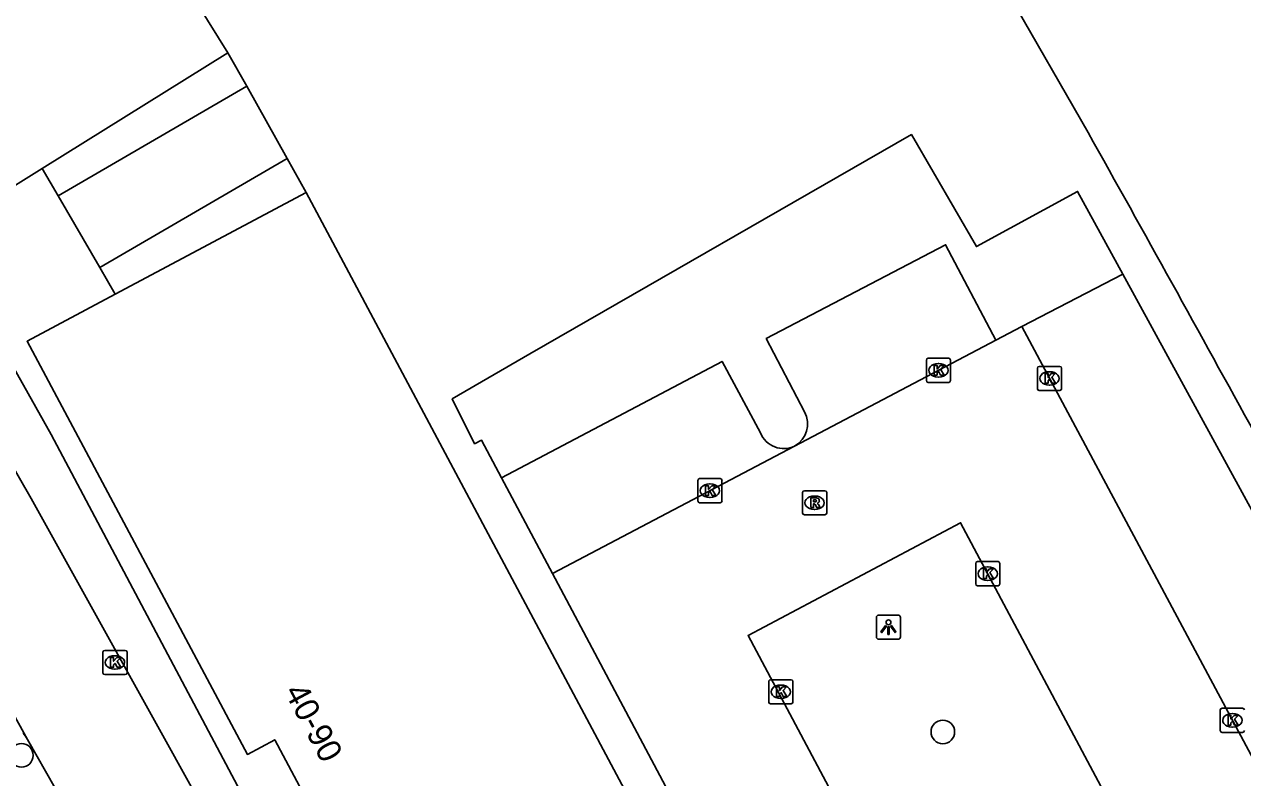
# Model space of a CAD drawing. Extents: x 160304 to 160954, y 383686 to 384161.
# Drawn here: x 160761.5 to 160812, y 383967.6 to 383998.8 of the extents above; entities that cross this region are included whole.
import ezdxf

# ---------------------------------------------------------------- set-up
doc = ezdxf.new("R2010")
doc.units = 0
for name, color, linetype in [('IMGEO_Boom', 7, 'Continuous'), ('IMGEO_Kolk', 7, 'Continuous'), ('IMGEO_Lichtpunt', 7, 'Continuous'), ('IMGEO_Pand', 7, 'Continuous'), ('IMGEO_Pand_nummerreeks', 7, 'Continuous'), ('IMGEO_Pand_overbouw', 7, 'Continuous'), ('IMGEO_Parkeervlak_open', 7, 'Continuous'), ('IMGEO_Rijbaan_lokaal_open', 7, 'Continuous'), ('IMGEO_Rioolput', 7, 'Continuous'), ('IMGEO_Voetpad_open', 7, 'Continuous')]:
    doc.layers.add(name, color=color, linetype=linetype)

msp = doc.modelspace()

# ---------------------------------------------------------------- linework, layer by layer
at = {"layer": 'IMGEO_Boom'}
for centre in [(160799.535, 383969.454), (160761.339, 383968.483)]:
    msp.add_circle(centre, 0.489, dxfattribs=at)
at = {"layer": 'IMGEO_Kolk'}
for p, q in [((160798.927, 383984.937), (160799.779, 383984.937)), ((160798.852, 383984.011), (160798.852, 383984.863)), ((160799.34, 383984.717), (160799.365, 383984.717)), ((160799.853, 383984.863), (160799.853, 383984.011)), ((160803.456, 383983.674), (160803.456, 383984.526)), ((160803.531, 383984.6), (160804.383, 383984.6)), ((160804.457, 383984.526), (160804.457, 383983.674)), ((160799.779, 383983.937), (160798.927, 383983.937)), ((160799.363, 383984.157), (160799.338, 383984.157)), ((160803.944, 383984.38), (160803.969, 383984.38)), ((160804.383, 383983.6), (160803.531, 383983.6)), ((160803.967, 383983.82), (160803.942, 383983.82)), ((160789.38, 383979.024), (160789.38, 383979.876)), ((160789.455, 383979.95), (160790.307, 383979.95)), ((160790.381, 383979.876), (160790.381, 383979.024)), ((160789.868, 383979.73), (160789.893, 383979.73)), ((160790.307, 383978.95), (160789.455, 383978.95)), ((160789.891, 383979.17), (160789.866, 383979.17)), ((160800.897, 383975.584), (160800.897, 383976.436)), ((160800.972, 383976.51), (160801.824, 383976.51)), ((160801.898, 383976.436), (160801.898, 383975.584)), ((160801.385, 383976.29), (160801.41, 383976.29)), ((160801.824, 383975.51), (160800.972, 383975.51)), ((160801.408, 383975.73), (160801.383, 383975.73)), ((160764.791, 383972.831), (160765.643, 383972.831)), ((160764.716, 383971.905), (160764.716, 383972.757)), ((160765.204, 383972.611), (160765.229, 383972.611)), ((160765.717, 383972.757), (160765.717, 383971.905)), ((160765.643, 383971.831), (160764.791, 383971.831)), ((160765.227, 383972.051), (160765.202, 383972.051)), ((160792.32, 383970.69), (160792.32, 383971.542)), ((160792.395, 383971.616), (160793.247, 383971.616)), ((160792.808, 383971.396), (160792.833, 383971.396)), ((160793.321, 383971.542), (160793.321, 383970.69)), ((160792.831, 383970.836), (160792.806, 383970.836)), ((160793.247, 383970.616), (160792.395, 383970.616)), ((160811.037, 383969.51), (160811.037, 383970.362)), ((160811.112, 383970.436), (160811.964, 383970.436)), ((160811.525, 383970.216), (160811.55, 383970.216)), ((160811.964, 383969.436), (160811.112, 383969.436)), ((160811.548, 383969.656), (160811.523, 383969.656))]:
    msp.add_line(p, q, dxfattribs=at)
for points in [[(160798.927, 383984.937), (160799.779, 383984.937)], [(160798.852, 383984.011), (160798.852, 383984.863)], [(160799.173, 383984.637), (160799.296, 383984.637), (160799.296, 383984.486), (160799.426, 383984.637), (160799.59, 383984.637), (160799.444, 383984.486), (160799.597, 383984.237), (160799.445, 383984.237), (160799.36, 383984.401), (160799.296, 383984.334), (160799.296, 383984.237), (160799.173, 383984.237), (160799.173, 383984.637)], [(160799.853, 383984.863), (160799.853, 383984.011)], [(160803.456, 383983.674), (160803.456, 383984.526)], [(160803.531, 383984.6), (160804.383, 383984.6)], [(160804.457, 383984.526), (160804.457, 383983.674)], [(160799.779, 383983.937), (160798.927, 383983.937)], [(160803.777, 383984.3), (160803.9, 383984.3), (160803.9, 383984.149), (160804.03, 383984.3), (160804.194, 383984.3), (160804.048, 383984.149), (160804.201, 383983.9), (160804.049, 383983.9), (160803.964, 383984.064), (160803.9, 383983.997), (160803.9, 383983.9), (160803.777, 383983.9), (160803.777, 383984.3)], [(160804.383, 383983.6), (160803.531, 383983.6)], [(160789.38, 383979.024), (160789.38, 383979.876)], [(160789.455, 383979.95), (160790.307, 383979.95)], [(160790.381, 383979.876), (160790.381, 383979.024)], [(160789.701, 383979.65), (160789.824, 383979.65), (160789.824, 383979.499), (160789.954, 383979.65), (160790.118, 383979.65), (160789.972, 383979.499), (160790.125, 383979.25), (160789.973, 383979.25), (160789.888, 383979.414), (160789.824, 383979.347), (160789.824, 383979.25), (160789.701, 383979.25), (160789.701, 383979.65)], [(160790.307, 383978.95), (160789.455, 383978.95)], [(160800.897, 383975.584), (160800.897, 383976.436)], [(160800.972, 383976.51), (160801.824, 383976.51)], [(160801.898, 383976.436), (160801.898, 383975.584)], [(160801.218, 383976.21), (160801.341, 383976.21), (160801.341, 383976.059), (160801.471, 383976.21), (160801.635, 383976.21), (160801.489, 383976.059), (160801.642, 383975.81), (160801.49, 383975.81), (160801.405, 383975.974), (160801.341, 383975.907), (160801.341, 383975.81), (160801.218, 383975.81), (160801.218, 383976.21)], [(160801.824, 383975.51), (160800.972, 383975.51)], [(160764.791, 383972.831), (160765.643, 383972.831)], [(160764.716, 383971.905), (160764.716, 383972.757)], [(160765.037, 383972.531), (160765.16, 383972.531), (160765.16, 383972.38), (160765.29, 383972.531), (160765.454, 383972.531), (160765.308, 383972.38), (160765.461, 383972.131), (160765.309, 383972.131), (160765.224, 383972.295), (160765.16, 383972.228), (160765.16, 383972.131), (160765.037, 383972.131), (160765.037, 383972.531)], [(160765.717, 383972.757), (160765.717, 383971.905)], [(160765.643, 383971.831), (160764.791, 383971.831)], [(160792.32, 383970.69), (160792.32, 383971.542)], [(160792.395, 383971.616), (160793.247, 383971.616)], [(160792.641, 383971.316), (160792.764, 383971.316), (160792.764, 383971.165), (160792.894, 383971.316), (160793.058, 383971.316), (160792.912, 383971.165), (160793.065, 383970.916), (160792.913, 383970.916), (160792.828, 383971.08), (160792.764, 383971.013), (160792.764, 383970.916), (160792.641, 383970.916), (160792.641, 383971.316)], [(160793.321, 383971.542), (160793.321, 383970.69)], [(160793.247, 383970.616), (160792.395, 383970.616)], [(160811.037, 383969.51), (160811.037, 383970.362)], [(160811.112, 383970.436), (160811.964, 383970.436)], [(160811.358, 383970.136), (160811.481, 383970.136), (160811.481, 383969.985), (160811.611, 383970.136), (160811.775, 383970.136), (160811.629, 383969.985), (160811.782, 383969.736), (160811.63, 383969.736), (160811.545, 383969.9), (160811.481, 383969.833), (160811.481, 383969.736), (160811.358, 383969.736), (160811.358, 383970.136)], [(160811.964, 383969.436), (160811.112, 383969.436)]]:
    msp.add_lwpolyline(points, dxfattribs=at)
for centre, start, end in [((160798.929, 383984.861), 91.552, 178.448), ((160798.929, 383984.861), 91.552, 178.448), ((160799.777, 383984.861), 1.552, 88.448), ((160799.777, 383984.861), 1.552, 88.448), ((160803.533, 383984.524), 91.552, 178.448), ((160803.533, 383984.524), 91.552, 178.448), ((160804.381, 383984.524), 1.552, 88.448), ((160804.381, 383984.524), 1.552, 88.448), ((160798.929, 383984.013), 181.552, 268.448), ((160798.929, 383984.013), 181.552, 268.448), ((160799.777, 383984.013), 271.552, 358.448), ((160799.777, 383984.013), 271.552, 358.448), ((160803.533, 383983.676), 181.552, 268.448), ((160803.533, 383983.676), 181.552, 268.448), ((160804.381, 383983.676), 271.552, 358.448), ((160804.381, 383983.676), 271.552, 358.448), ((160789.457, 383979.874), 91.552, 178.448), ((160789.457, 383979.874), 91.552, 178.448), ((160790.305, 383979.874), 1.552, 88.448), ((160790.305, 383979.874), 1.552, 88.448), ((160789.457, 383979.026), 181.552, 268.448), ((160789.457, 383979.026), 181.552, 268.448), ((160790.305, 383979.026), 271.552, 358.448), ((160790.305, 383979.026), 271.552, 358.448), ((160800.974, 383976.434), 91.552, 178.448), ((160800.974, 383976.434), 91.552, 178.448), ((160801.822, 383976.434), 1.552, 88.448), ((160801.822, 383976.434), 1.552, 88.448), ((160800.974, 383975.586), 181.552, 268.448), ((160800.974, 383975.586), 181.552, 268.448), ((160801.822, 383975.586), 271.552, 358.448), ((160801.822, 383975.586), 271.552, 358.448), ((160764.793, 383972.755), 91.552, 178.448), ((160764.793, 383972.755), 91.552, 178.448), ((160765.641, 383972.755), 1.552, 88.448), ((160765.641, 383972.755), 1.552, 88.448), ((160764.793, 383971.907), 181.552, 268.448), ((160764.793, 383971.907), 181.552, 268.448), ((160765.641, 383971.907), 271.552, 358.448), ((160765.641, 383971.907), 271.552, 358.448), ((160792.397, 383971.54), 91.552, 178.448), ((160792.397, 383971.54), 91.552, 178.448), ((160793.245, 383971.54), 1.552, 88.448), ((160793.245, 383971.54), 1.552, 88.448), ((160792.397, 383970.692), 181.552, 268.448), ((160792.397, 383970.692), 181.552, 268.448), ((160793.245, 383970.692), 271.552, 358.448), ((160793.245, 383970.692), 271.552, 358.448), ((160811.114, 383970.36), 91.552, 178.448), ((160811.114, 383970.36), 91.552, 178.448), ((160811.962, 383970.36), 1.552, 88.448), ((160811.962, 383970.36), 1.552, 88.448), ((160811.114, 383969.512), 181.552, 268.448), ((160811.114, 383969.512), 181.552, 268.448), ((160811.962, 383969.512), 271.552, 358.448), ((160811.962, 383969.512), 271.552, 358.448)]:
    msp.add_arc(centre, 0.0765, start, end, dxfattribs=at)
for centre, major_axis, ratio, start_param, end_param in [((160799.339, 383984.437), (-0.387, 0.002), 0.722429, 4.712389, 7.853982), ((160799.364, 383984.437), (-0.39, 0.002), 0.717154, 1.570796, 4.712389), ((160803.943, 383984.1), (-0.387, 0.002), 0.722429, 4.712389, 7.853982), ((160803.968, 383984.1), (-0.39, 0.002), 0.717154, 1.570796, 4.712389), ((160789.867, 383979.45), (-0.387, 0.002), 0.722429, 4.712389, 7.853982), ((160789.892, 383979.45), (-0.39, 0.002), 0.717154, 1.570796, 4.712389), ((160801.384, 383976.01), (-0.387, 0.002), 0.722429, 4.712389, 7.853982), ((160801.409, 383976.01), (-0.39, 0.002), 0.717154, 1.570796, 4.712389), ((160765.203, 383972.331), (-0.387, 0.002), 0.722429, 4.712389, 7.853982), ((160765.228, 383972.331), (-0.39, 0.002), 0.717154, 1.570796, 4.712389), ((160792.807, 383971.116), (-0.387, 0.002), 0.722429, 4.712389, 7.853982), ((160792.832, 383971.116), (-0.39, 0.002), 0.717154, 1.570796, 4.712389), ((160811.524, 383969.936), (-0.387, 0.002), 0.722429, 4.712389, 7.853982), ((160811.549, 383969.936), (-0.39, 0.002), 0.717154, 1.570796, 4.712389)]:
    msp.add_ellipse(centre, major_axis=major_axis, ratio=ratio, start_param=start_param, end_param=end_param, dxfattribs=at)
at = {"layer": 'IMGEO_Lichtpunt'}
for p, q in [((160796.783, 383974.197), (160796.783, 383973.39)), ((160796.783, 383974.197), (160796.783, 383973.39)), ((160797.685, 383974.292), (160796.877, 383974.292)), ((160797.685, 383974.292), (160796.877, 383974.292)), ((160797.779, 383973.39), (160797.779, 383974.197)), ((160797.779, 383973.39), (160797.779, 383974.197)), ((160796.877, 383973.296), (160797.685, 383973.296)), ((160796.877, 383973.296), (160797.685, 383973.296))]:
    msp.add_line(p, q, dxfattribs=at)
for points in [[(160797.157, 383973.861), (160797.196, 383973.833), (160797.008, 383973.571), (160796.97, 383973.598), (160797.157, 383973.861)], [(160797.259, 383973.813), (160797.306, 383973.813), (160797.306, 383973.491), (160797.259, 383973.491), (160797.259, 383973.813)], [(160797.369, 383973.833), (160797.407, 383973.86), (160797.594, 383973.598), (160797.555, 383973.57), (160797.369, 383973.833)]]:
    msp.add_lwpolyline(points, dxfattribs=at)
msp.add_circle((160797.282, 383973.995), 0.0994, dxfattribs=at)
for centre, start, end in [((160796.877, 383974.197), 90, 180), ((160796.877, 383974.197), 90, 180), ((160797.685, 383974.197), 0, 90), ((160797.685, 383974.197), 0, 90), ((160796.877, 383973.39), 180, 270), ((160796.877, 383973.39), 180, 270), ((160797.685, 383973.39), 270, 0), ((160797.685, 383973.39), 270, 360)]:
    msp.add_arc(centre, 0.0946, start, end, dxfattribs=at)
at = {"layer": 'IMGEO_Pand'}
for points in [[(160744.525, 384030.508), (160747.806, 384032.552), (160748.032, 384032.693), (160769.901, 383997.598), (160762.198, 383992.799), (160758.718, 383990.63), (160748.428, 384007.142), (160749.512, 384007.817), (160744.868, 384015.27), (160743.822, 384014.618), (160737.034, 384025.51)], [(160797.022, 384009.201), (160802.29, 384000), (160805.557, 383994.294)], [(160772.358, 383993.214), (160764.587, 383988.694), (160762.857, 383991.667), (160770.681, 383996.207), (160772.358, 383993.214)], [(160780.961, 383949.257), (160774.814, 383960.781), (160775.968, 383961.397), (160771.843, 383969.13), (160770.706, 383968.524), (160761.577, 383985.638), (160765.23, 383987.587), (160773.144, 383991.809), (160792.547, 383955.437), (160789.439, 383953.779)]]:
    msp.add_lwpolyline(points, dxfattribs=at)
msp.add_arc((159123.204, 383053.921), 1927.333, 28.779303, 29.203562, dxfattribs=at)
at = {"layer": 'IMGEO_Pand_overbouw'}
for points in [[(160770.681, 383996.207), (160769.901, 383997.598), (160762.198, 383992.799), (160762.857, 383991.667)], [(160764.587, 383988.694), (160765.23, 383987.587), (160773.144, 383991.809), (160772.358, 383993.214)]]:
    msp.add_lwpolyline(points, close=True, dxfattribs=at)
at = {"layer": 'IMGEO_Parkeervlak_open'}
for points in [[(160806.997, 383988.421), (160817.543, 383969.142), (160814.927, 383967.761), (160817.081, 383963.773), (160819.647, 383965.18), (160824.324, 383956.417), (160820.023, 383954.079)], [(160783.352, 383976.011), (160781.236, 383979.986)]]:
    msp.add_lwpolyline(points, dxfattribs=at)
at = {"layer": 'IMGEO_Rijbaan_lokaal_open'}
for points in [[(160750.394, 383998.089), (160755.01, 383990.819), (160761.742, 383979.128), (160773.706, 383957.589), (160774.263, 383956.197)], [(160747.642, 383992.973), (160752.22, 383985.59), (160753.76, 383982.944), (160760.841, 383970.491), (160761.594, 383969.14)], [(160802.804, 383986.252), (160801.739, 383985.691)], [(160820.023, 383954.079), (160802.804, 383986.252)], [(160801.739, 383985.691), (160793.392, 383981.297)], [(160793.392, 383981.297), (160783.352, 383976.011)], [(160802.524, 383952.671), (160791.461, 383973.452), (160800.275, 383978.122), (160811.351, 383957.327), (160802.524, 383952.671)], [(160794.841, 383954.422), (160783.352, 383976.011)], [(160761.594, 383969.14), (160762.737, 383967.125)]]:
    msp.add_lwpolyline(points, dxfattribs=at)
at = {"layer": 'IMGEO_Rioolput'}
for p, q in [((160793.72, 383978.522), (160793.72, 383979.374)), ((160793.795, 383979.448), (160794.647, 383979.448)), ((160794.721, 383979.374), (160794.721, 383978.522)), ((160794.208, 383979.228), (160794.233, 383979.228)), ((160794.647, 383978.448), (160793.795, 383978.448)), ((160794.231, 383978.668), (160794.206, 383978.668))]:
    msp.add_line(p, q, dxfattribs=at)
for points in [[(160793.72, 383978.522), (160793.72, 383979.374)], [(160793.795, 383979.448), (160794.647, 383979.448)], [(160794.721, 383979.374), (160794.721, 383978.522)], [(160794.309, 383979.146), (160794.057, 383979.148), (160794.057, 383978.748)], [(160794.057, 383978.748), (160794.181, 383978.748), (160794.181, 383978.91), (160794.192, 383978.91)], [(160794.235, 383979.067), (160794.181, 383979.067), (160794.181, 383978.986)], [(160794.181, 383978.986), (160794.233, 383978.986)], [(160794.239, 383978.881), (160794.31, 383978.748), (160794.45, 383978.748), (160794.385, 383978.874)], [(160794.647, 383978.448), (160793.795, 383978.448)]]:
    msp.add_lwpolyline(points, dxfattribs=at)
for centre, radius, start, end in [((160793.797, 383979.372), 0.0765, 91.552, 178.448), ((160793.797, 383979.372), 0.0765, 91.552, 178.448), ((160794.645, 383979.372), 0.0765, 1.552, 88.448), ((160794.645, 383979.372), 0.0765, 1.552, 88.448), ((160794.191, 383978.857), 0.0533, 26.0293, 88.6989), ((160794.217, 383979.175), 0.19, 274.7715, 282.9687), ((160794.241, 383978.971), 0.0964, 77.0061, 93.1865), ((160794.255, 383979.028), 0.0378, 276.6634, 79.6772), ((160794.308, 383979.036), 0.109, 350.3612, 89.416), ((160794.306, 383979.036), 0.112, 277.5842, 350.9817), ((160794.29, 383978.821), 0.108, 29.5134, 73.7905), ((160793.797, 383978.524), 0.0765, 181.552, 268.448), ((160793.797, 383978.524), 0.0765, 181.552, 268.448), ((160794.645, 383978.524), 0.0765, 271.552, 358.448), ((160794.645, 383978.524), 0.0765, 271.552, 358.448)]:
    msp.add_arc(centre, radius, start, end, dxfattribs=at)
for centre, major_axis, ratio, start_param, end_param in [((160794.207, 383978.948), (-0.387, 0.002), 0.722429, 4.712389, 7.853982), ((160794.232, 383978.948), (-0.39, 0.002), 0.717154, 1.570796, 4.712389)]:
    msp.add_ellipse(centre, major_axis=major_axis, ratio=ratio, start_param=start_param, end_param=end_param, dxfattribs=at)
at = {"layer": 'IMGEO_Voetpad_open'}
for points in [[(160738.593, 384021.168), (160751.74, 384000), (160757.862, 383990.144), (160762.576, 383981.777), (160780.073, 383948.774)], [(160781.236, 383979.986), (160780.405, 383981.548), (160780.126, 383981.396), (160779.201, 383983.25), (160782.415, 383985.126), (160798.232, 383994.207), (160800.93, 383989.567), (160805.122, 383991.849), (160806.997, 383988.421)], [(160793.8, 383982.71), (160792.215, 383985.751), (160799.649, 383989.64), (160801.739, 383985.691)], [(160806.997, 383988.421), (160802.804, 383986.252)], [(160781.236, 383979.986), (160790.382, 383984.808), (160791.98, 383981.842)], [(160761.594, 383969.14), (160761.51, 383969.275), (160761.414, 383969.402)]]:
    msp.add_lwpolyline(points, dxfattribs=at)
for centre, radius, start, end in [((160792.88, 383982.21), 1.047, 299.2691, 28.5191), ((160792.936, 383982.218), 1.027, 201.4532, 296.3359)]:
    msp.add_arc(centre, radius, start, end, dxfattribs=at)

# ---------------------------------------------------------------- texts
at = {"layer": 'IMGEO_Pand_nummerreeks'}
msp.add_text('40-90', height=1, rotation=298.0168, dxfattribs=at).set_placement((160772.215, 383971.123))

doc.saveas('drawing.dxf')
